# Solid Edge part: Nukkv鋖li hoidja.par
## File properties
Author: Türk
Template: Iso Part.par
Last saved by: Türk
Revision: 8
Application: Solid Edge
Accuracy: 0,990
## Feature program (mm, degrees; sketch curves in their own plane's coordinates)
sketch for "unnamed Hole 1" plane through (0, 0, 30) normal (0, 0, 1) x-axis (1, 0, 0)
hole "unnamed Hole 1" finite
sketch for "Hole_1" plane through (0, 0, 30) normal (0, 0, 1) x-axis (1, 0, 0)
hole "Hole_1" diameter 6 finite
pattern "unnamed Pattern 1" of "Hole_1", "unnamed Hole 1"
thread "unnamed Thread 1"
thread "unnamed Thread 2"
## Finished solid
Body 1: solid body, 16 faces, 34 edges, 20 vertices.
  Faces by surface: plane 11, cylinder 5
  Edges by curve: line 24, circle 8, ellipse 2
Bounding box of the edges (mm): 65.000 x 20.000 x 30.000, from (-32.5, -10, 0) to (32.5, 10, 30).
Cylindrical faces by radius (mm): R2.7295 x2, R6.35 x2, R12.5 x1
Planar faces by outward normal: +x 1, +y 1, +z 3, -x 1, -y 1, -z 2, oblique 2
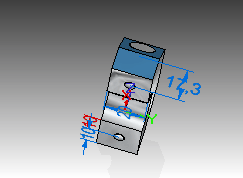
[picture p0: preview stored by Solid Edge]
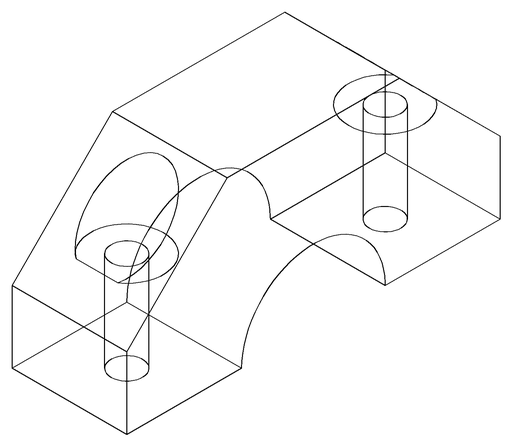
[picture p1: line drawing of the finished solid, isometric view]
